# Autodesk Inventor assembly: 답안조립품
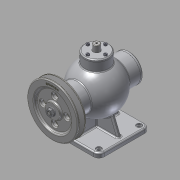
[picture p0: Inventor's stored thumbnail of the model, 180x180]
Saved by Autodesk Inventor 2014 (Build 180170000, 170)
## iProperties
Created: 2015-10
Part Number: 답안조립품
Document SubType Name: Assembly
Designer: youjin19
Author: youjin19
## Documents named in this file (19)
- C:\Users\youjin19\Desktop\451010V1017\답안조립품.iam
- C:\Users\youjin19\Desktop\451010V1017\본체.ipt
- C:\Users\youjin19\Desktop\451010V1017\앞커버.ipt
- C:\Users\youjin19\Desktop\451010V1017\볼트 M4 x 16.ipt
- C:\Users\youjin19\Desktop\451010V1017\뒤커버.ipt
- C:\Users\youjin19\Desktop\451010V1017\상부커버.ipt
- C:\Users\youjin19\Desktop\451010V1017\볼트 M 4 x 12.ipt
- C:\Users\youjin19\Desktop\451010V1017\오일실 15 30 7.ipt
- C:\Users\youjin19\Desktop\451010V1017\베어링- 6202.ipt
- KS B 2023 - 6202 - 15 x 35 x 11 - 7.8.ipt
- C:\Users\youjin19\Desktop\451010V1017\편심축.ipt
- C:\Users\youjin19\Desktop\451010V1017\부시.ipt
- C:\Users\youjin19\Desktop\451010V1017\멈춤링- 15 x 1.ipt
- C:\Users\youjin19\Desktop\451010V1017\멈춤링- 35x1.6.ipt
- KS B 1336 - 35x1.6.ipt
- C:\Users\youjin19\Desktop\451010V1017\키 4 x 4 x 12.ipt
- C:\Users\youjin19\Desktop\451010V1017\V-벨트풀리.ipt
- C:\Users\youjin19\Desktop\451010V1017\너트 M8.ipt
- C:\Users\youjin19\Desktop\451010V1017\슬라이드.ipt
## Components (16 placed, 5 different names)
1. KS B 2023 - 6202 - 15 x 35 x 11 - 7.8:1 — Mate:12, Mate:13, Mate:18, Mate:19, Angle:3
2. KS B 2023 - 6202 - 15 x 35 x 11 - 7.8:2 — Mate:14, Mate:15, Mate:21, Angle:4
3. KS B 1336 - 35x1.6:1 — Mate:21, Mate:22, Angle:2
4. V-벨트풀리:1 — Mate:26, Mate:27, Mate:28
5. ISO 4762 M4 x 16:1 — Insert:1
6. ISO 4762 M4 x 16:2
7. ISO 4762 M4 x 16:3
8. ISO 4762 M4 x 16:4
9. ISO 4762 M4 x 16:5 — Insert:2
10. ISO 4762 M4 x 16:6
11. ISO 4762 M4 x 16:7
12. ISO 4762 M4 x 16:8
13. KS B 1021 - 에 따름 ISO 1207 - 미터 A  M 4 x 12:1 — Insert:3
14. KS B 1021 - 에 따름 ISO 1207 - 미터 A  M 4 x 12:2
15. KS B 1021 - 에 따름 ISO 1207 - 미터 A  M 4 x 12:3
16. KS B 1021 - 에 따름 ISO 1207 - 미터 A  M 4 x 12:4
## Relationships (17: Mate 11, Insert 3, Angle 3)
- Insert:1: ISO 4762 M4 x 16:1
- Insert:2: ISO 4762 M4 x 16:5
- Insert:3: KS B 1021 - 에 따름 ISO 1207 - 미터 A  M 4 x 12:1
- Mate:12: KS B 2023 - 6202 - 15 x 35 x 11 - 7.8:1
- Mate:13: KS B 2023 - 6202 - 15 x 35 x 11 - 7.8:1
- Mate:14: KS B 2023 - 6202 - 15 x 35 x 11 - 7.8:2
- Mate:15: KS B 2023 - 6202 - 15 x 35 x 11 - 7.8:2
- Mate:18: KS B 2023 - 6202 - 15 x 35 x 11 - 7.8:1
- Mate:19: KS B 2023 - 6202 - 15 x 35 x 11 - 7.8:1
- Mate:21: KS B 2023 - 6202 - 15 x 35 x 11 - 7.8:2 ↔ KS B 1336 - 35x1.6:1
- Mate:22: KS B 1336 - 35x1.6:1
- Angle:2: KS B 1336 - 35x1.6:1
- Angle:3: KS B 2023 - 6202 - 15 x 35 x 11 - 7.8:1
- Angle:4: KS B 2023 - 6202 - 15 x 35 x 11 - 7.8:2
- Mate:26: V-벨트풀리:1
- Mate:27: V-벨트풀리:1
- Mate:28: V-벨트풀리:1
